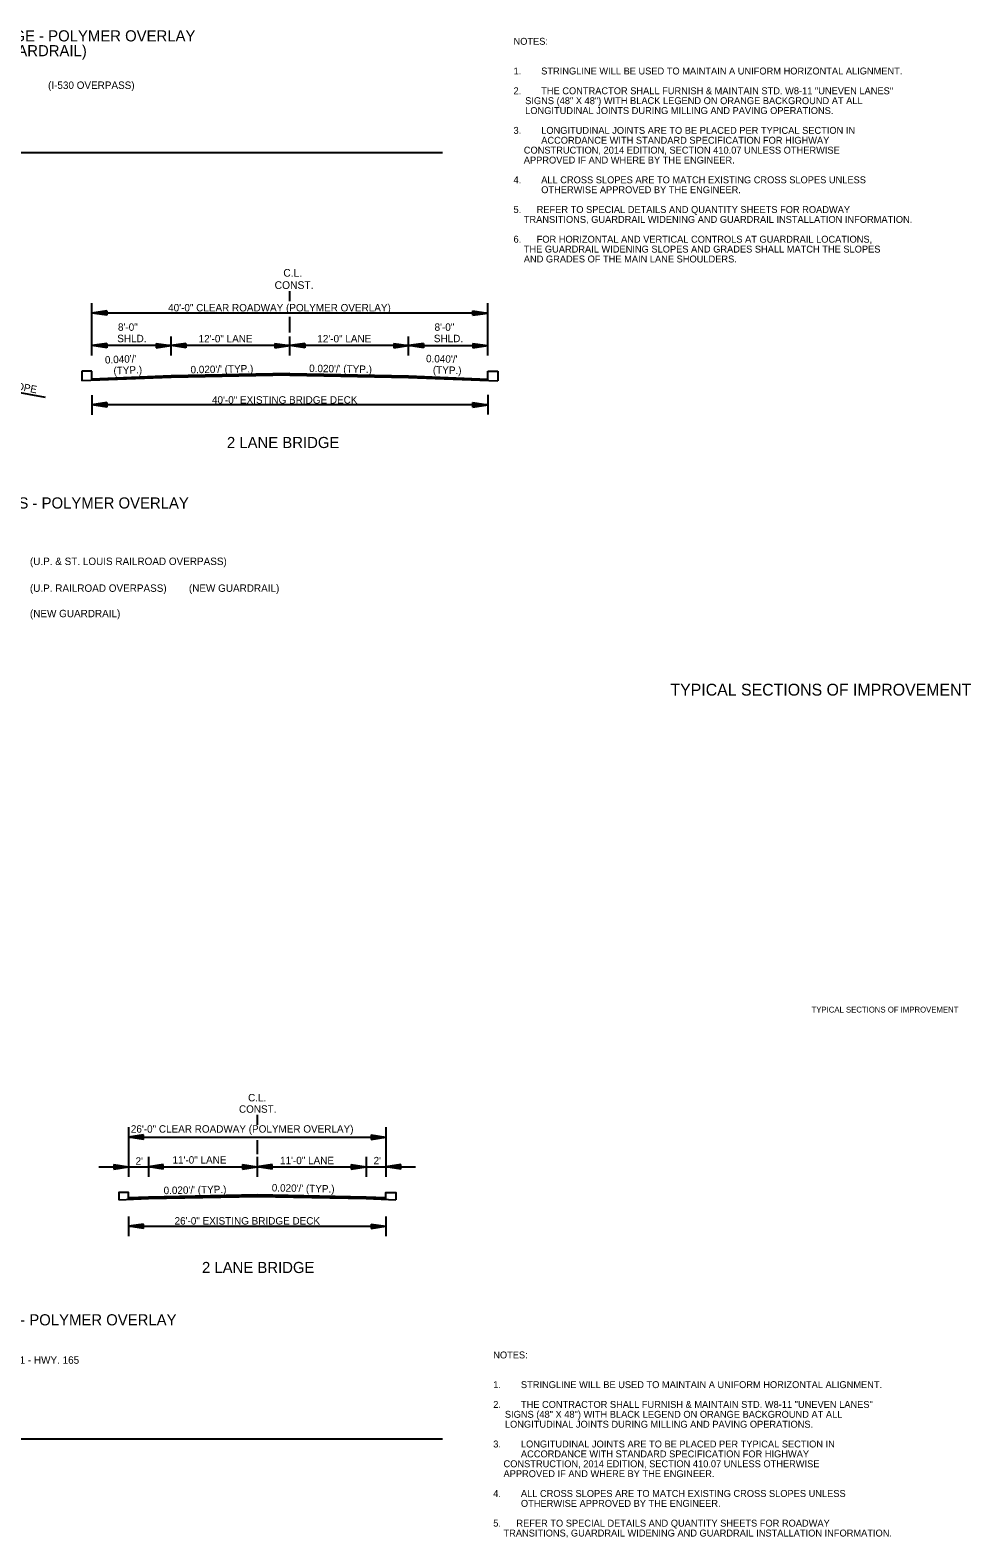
# Model space of a CAD drawing. Extents: x 545241 to 1930787, y -1971772 to 596640.
# Drawn here: x 547317 to 548268, y -1951823 to -1950299 of the extents above; entities that cross this region are included whole.
import ezdxf

# ---------------------------------------------------------------- set-up
doc = ezdxf.new("R2010")
doc.units = 0
for name, color, linetype in [('R_Border', 7, 'Continuous'), ('R_Border Notes', 7, 'Continuous'), ('R_Border Prem', 7, 'Continuous'), ('R_Draft', 7, 'Continuous')]:
    doc.layers.add(name, color=color, linetype=linetype)

# ---------------------------------------------------------------- blocks, each defined once
blk = doc.blocks.new('ARROW')
at = {"layer": 'R_Draft'}
for p, q in [((-2, 0.3), (0, 0)), ((-2, 0.3), (-2, -0.3)), ((-2, 0.25), (-0.334, 0)), ((-2, 0.199), (-0.678, 0)), ((-2, 0.149), (-1.011, 0)), ((-2, 0.097), (-1.35, 0)), ((-2, 0.047), (-1.684, 0)), ((-2, -0.3), (0, 0)), ((-2, -0.098), (-1.35, 0)), ((-2, -0.199), (-0.678, 0)), ((-2, -0.25), (-0.334, 0)), ((-2, -0.149), (-1.011, 0)), ((-2, -0.047), (-1.684, 0))]:
    blk.add_line(p, q, dxfattribs=at)

msp = doc.modelspace()

# ---------------------------------------------------------------- linework, layer by layer
at = {"layer": 'R_Border'}
for p, q in [((546887.2, -1950422.9), (547733.9, -1950422.9)), ((547369.3, -1950643.9), (547369.3, -1950653.7)), ((547379.5, -1950643.9), (547369.3, -1950643.9)), ((547379.5, -1950653.3), (547379.5, -1950643.9)), ((547779.5, -1950653.3), (547779.5, -1950643.9)), ((547779.5, -1950643.9), (547789.7, -1950643.9)), ((547789.7, -1950643.9), (547789.7, -1950653.7)), ((547546.6, -1951395.5), (547546.6, -1951405.5)), ((547416.6, -1951408), (547416.6, -1951458)), ((547676.6, -1951408), (547676.6, -1951458)), ((547416.6, -1951418), (547676.6, -1951418)), ((547546.6, -1951421), (547546.6, -1951435)), ((547436.6, -1951438), (547436.6, -1951458)), ((547546.6, -1951438), (547546.6, -1951458)), ((547656.6, -1951438), (547656.6, -1951458)), ((547386.6, -1951448), (547706.6, -1951448)), ((547416.6, -1951498), (547416.6, -1951518)), ((547676.6, -1951498), (547676.6, -1951518)), ((547416.6, -1951508), (547676.6, -1951508)), ((546887.2, -1951722.9), (547733.9, -1951722.9))]:
    msp.add_line(p, q, dxfattribs=at)
for points in [[(547416.6, -1951480.5), (547416.6, -1951474), (547406.6, -1951474), (547406.6, -1951481.2)], [(547406.6, -1951481.2), (547436.6, -1951480), (547546.6, -1951477.8), (547656.6, -1951480), (547686.6, -1951481.2)], [(547416.6, -1951479), (547436.6, -1951478.2), (547546.6, -1951476), (547656.6, -1951478.2), (547676.6, -1951479)], [(547416.6, -1951479.3), (547436.6, -1951478.5), (547546.6, -1951476.3), (547656.6, -1951478.5), (547676.6, -1951479.3)], [(547416.6, -1951479.6), (547436.6, -1951478.8), (547546.6, -1951476.6), (547656.6, -1951478.8), (547676.6, -1951479.6)], [(547416.6, -1951479.9), (547436.6, -1951479.1), (547546.6, -1951476.9), (547656.6, -1951479.1), (547676.6, -1951479.9)], [(547416.6, -1951480.2), (547436.6, -1951479.4), (547546.6, -1951477.2), (547656.6, -1951479.4), (547676.6, -1951480.2)], [(547416.6, -1951480.5), (547436.6, -1951479.7), (547546.6, -1951477.5), (547656.6, -1951479.7), (547676.6, -1951480.5)], [(547676.6, -1951480.5), (547676.6, -1951474), (547686.6, -1951474), (547686.6, -1951481.2)]]:
    msp.add_lwpolyline(points, dxfattribs=at)
at = {"layer": 'R_Draft'}
for p, q in [((547579.5, -1950572.9), (547579.5, -1950562.9)), ((547379.5, -1950627.9), (547379.5, -1950575.2)), ((547394.5, -1950582.8), (547379.5, -1950585.1)), ((547779.5, -1950585.1), (547379.5, -1950585.1)), ((547394.5, -1950587.3), (547379.5, -1950585.1)), ((547394.5, -1950583.2), (547382, -1950585.1)), ((547394.5, -1950586.9), (547382, -1950585.1)), ((547394.5, -1950583.6), (547384.6, -1950585.1)), ((547394.5, -1950586.6), (547384.6, -1950585.1)), ((547394.5, -1950584), (547387.1, -1950585.1)), ((547394.5, -1950586.2), (547387.1, -1950585.1)), ((547394.5, -1950584.3), (547389.6, -1950585.1)), ((547394.5, -1950585.8), (547389.6, -1950585.1)), ((547394.5, -1950584.7), (547392.1, -1950585.1)), ((547394.5, -1950585.4), (547392.1, -1950585.1)), ((547394.5, -1950582.8), (547394.5, -1950587.3)), ((547579.5, -1950604.6), (547579.5, -1950589)), ((547764.5, -1950582.8), (547779.5, -1950585.1)), ((547764.5, -1950587.3), (547764.5, -1950582.8)), ((547764.5, -1950583.2), (547777, -1950585.1)), ((547764.5, -1950583.6), (547774.4, -1950585.1)), ((547764.5, -1950584), (547771.9, -1950585.1)), ((547764.5, -1950584.3), (547769.4, -1950585.1)), ((547764.5, -1950584.7), (547766.9, -1950585.1)), ((547764.5, -1950587.3), (547779.5, -1950585.1)), ((547764.5, -1950585.8), (547769.4, -1950585.1)), ((547764.5, -1950586.6), (547774.4, -1950585.1)), ((547764.5, -1950586.9), (547777, -1950585.1)), ((547764.5, -1950586.2), (547771.9, -1950585.1)), ((547764.5, -1950585.4), (547766.9, -1950585.1)), ((547779.5, -1950627.9), (547779.5, -1950575.2)), ((547394.5, -1950615.7), (547379.5, -1950617.9)), ((547459.5, -1950617.9), (547379.5, -1950617.9)), ((547394.5, -1950620.2), (547379.5, -1950617.9)), ((547394.5, -1950616), (547382, -1950617.9)), ((547394.5, -1950619.8), (547382, -1950617.9)), ((547394.5, -1950616.4), (547384.6, -1950617.9)), ((547394.5, -1950619.4), (547384.6, -1950617.9)), ((547394.5, -1950616.8), (547387.1, -1950617.9)), ((547394.5, -1950619), (547387.1, -1950617.9)), ((547394.5, -1950617.2), (547389.6, -1950617.9)), ((547394.5, -1950618.6), (547389.6, -1950617.9)), ((547394.5, -1950617.6), (547392.1, -1950617.9)), ((547394.5, -1950618.3), (547392.1, -1950617.9)), ((547394.5, -1950615.7), (547394.5, -1950620.2)), ((547444.5, -1950615.7), (547459.5, -1950617.9)), ((547444.5, -1950615.7), (547444.5, -1950620.2)), ((547444.5, -1950616), (547457, -1950617.9)), ((547444.5, -1950616.4), (547454.4, -1950617.9)), ((547444.5, -1950616.8), (547451.9, -1950617.9)), ((547444.5, -1950617.2), (547449.4, -1950617.9)), ((547444.5, -1950617.6), (547446.9, -1950617.9)), ((547444.5, -1950620.2), (547459.5, -1950617.9)), ((547444.5, -1950618.6), (547449.4, -1950617.9)), ((547444.5, -1950619.4), (547454.4, -1950617.9)), ((547444.5, -1950619.8), (547457, -1950617.9)), ((547444.5, -1950619), (547451.9, -1950617.9)), ((547444.5, -1950618.3), (547446.9, -1950617.9)), ((547459.5, -1950627.9), (547459.5, -1950608.7)), ((547474.5, -1950615.7), (547459.5, -1950617.9)), ((547579.5, -1950617.9), (547459.5, -1950617.9)), ((547474.5, -1950620.2), (547459.5, -1950617.9)), ((547474.5, -1950616), (547462, -1950617.9)), ((547474.5, -1950619.8), (547462, -1950617.9)), ((547474.5, -1950616.4), (547464.6, -1950617.9)), ((547474.5, -1950619.4), (547464.6, -1950617.9)), ((547474.5, -1950616.8), (547467.1, -1950617.9)), ((547474.5, -1950619), (547467.1, -1950617.9)), ((547474.5, -1950617.2), (547469.6, -1950617.9)), ((547474.5, -1950618.6), (547469.6, -1950617.9)), ((547474.5, -1950617.6), (547472.1, -1950617.9)), ((547474.5, -1950618.3), (547472.1, -1950617.9)), ((547474.5, -1950615.7), (547474.5, -1950620.2)), ((547564.5, -1950615.7), (547579.5, -1950617.9)), ((547564.5, -1950615.7), (547564.5, -1950620.2)), ((547564.5, -1950616), (547577, -1950617.9)), ((547564.5, -1950616.4), (547574.4, -1950617.9)), ((547564.5, -1950616.8), (547571.9, -1950617.9)), ((547564.5, -1950617.2), (547569.4, -1950617.9)), ((547564.5, -1950617.6), (547566.9, -1950617.9)), ((547564.5, -1950620.2), (547579.5, -1950617.9)), ((547564.5, -1950618.6), (547569.4, -1950617.9)), ((547564.5, -1950619.4), (547574.4, -1950617.9)), ((547564.5, -1950619.8), (547577, -1950617.9)), ((547564.5, -1950619), (547571.9, -1950617.9)), ((547564.5, -1950618.3), (547566.9, -1950617.9)), ((547579.5, -1950627.9), (547579.5, -1950608.7)), ((547594.5, -1950615.7), (547579.5, -1950617.9)), ((547699.5, -1950617.9), (547579.5, -1950617.9)), ((547594.5, -1950620.2), (547579.5, -1950617.9)), ((547594.5, -1950616), (547582, -1950617.9)), ((547594.5, -1950619.8), (547582, -1950617.9)), ((547594.5, -1950616.4), (547584.6, -1950617.9)), ((547594.5, -1950619.4), (547584.6, -1950617.9)), ((547594.5, -1950616.8), (547587.1, -1950617.9)), ((547594.5, -1950619), (547587.1, -1950617.9)), ((547594.5, -1950617.2), (547589.6, -1950617.9)), ((547594.5, -1950618.6), (547589.6, -1950617.9)), ((547594.5, -1950617.6), (547592.1, -1950617.9)), ((547594.5, -1950618.3), (547592.1, -1950617.9)), ((547594.5, -1950615.7), (547594.5, -1950620.2)), ((547684.5, -1950615.7), (547699.5, -1950617.9)), ((547684.5, -1950615.7), (547684.5, -1950620.2)), ((547684.5, -1950616), (547697, -1950617.9)), ((547684.5, -1950616.4), (547694.4, -1950617.9)), ((547684.5, -1950616.8), (547691.9, -1950617.9)), ((547684.5, -1950617.2), (547689.4, -1950617.9)), ((547684.5, -1950617.6), (547686.9, -1950617.9)), ((547684.5, -1950620.2), (547699.5, -1950617.9)), ((547684.5, -1950618.6), (547689.4, -1950617.9)), ((547684.5, -1950619.4), (547694.4, -1950617.9)), ((547684.5, -1950619.8), (547697, -1950617.9)), ((547684.5, -1950619), (547691.9, -1950617.9)), ((547684.5, -1950618.3), (547686.9, -1950617.9)), ((547699.5, -1950627.9), (547699.5, -1950608.7)), ((547714.5, -1950615.7), (547699.5, -1950617.9)), ((547699.5, -1950617.9), (547779.5, -1950617.9)), ((547714.5, -1950620.2), (547699.5, -1950617.9)), ((547714.5, -1950616), (547702, -1950617.9)), ((547714.5, -1950619.8), (547702, -1950617.9)), ((547714.5, -1950616.4), (547704.6, -1950617.9)), ((547714.5, -1950619.4), (547704.6, -1950617.9)), ((547714.5, -1950616.8), (547707.1, -1950617.9)), ((547714.5, -1950619), (547707.1, -1950617.9)), ((547714.5, -1950617.2), (547709.6, -1950617.9)), ((547714.5, -1950618.6), (547709.6, -1950617.9)), ((547714.5, -1950617.6), (547712.1, -1950617.9)), ((547714.5, -1950618.3), (547712.1, -1950617.9)), ((547714.5, -1950615.7), (547714.5, -1950620.2)), ((547764.5, -1950615.7), (547779.5, -1950617.9)), ((547764.5, -1950615.7), (547764.5, -1950620.2)), ((547764.5, -1950616), (547777, -1950617.9)), ((547764.5, -1950616.4), (547774.4, -1950617.9)), ((547764.5, -1950616.8), (547771.9, -1950617.9)), ((547764.5, -1950617.2), (547769.4, -1950617.9)), ((547764.5, -1950617.6), (547766.9, -1950617.9)), ((547764.5, -1950620.2), (547779.5, -1950617.9)), ((547764.5, -1950618.6), (547769.4, -1950617.9)), ((547764.5, -1950619.4), (547774.4, -1950617.9)), ((547764.5, -1950619.8), (547777, -1950617.9)), ((547764.5, -1950619), (547771.9, -1950617.9)), ((547764.5, -1950618.3), (547766.9, -1950617.9)), ((547459.5, -1950650.1), (547369.3, -1950653.7)), ((547459.5, -1950648.6), (547379.5, -1950651.8)), ((547459.5, -1950648.9), (547379.5, -1950652.1)), ((547459.5, -1950649.2), (547379.5, -1950652.4)), ((547459.5, -1950649.5), (547379.5, -1950652.7)), ((547459.5, -1950649.8), (547379.5, -1950653)), ((547579.5, -1950646.2), (547459.5, -1950648.6)), ((547579.5, -1950646.5), (547459.5, -1950648.9)), ((547579.5, -1950646.8), (547459.5, -1950649.2)), ((547579.5, -1950647.1), (547459.5, -1950649.5)), ((547579.5, -1950647.4), (547459.5, -1950649.8)), ((547579.5, -1950647.7), (547459.5, -1950650.1)), ((547579.5, -1950647.9), (547459.5, -1950650.3)), ((547579.5, -1950646.2), (547699.5, -1950648.6)), ((547579.5, -1950646.5), (547699.5, -1950648.9)), ((547579.5, -1950646.8), (547699.5, -1950649.2)), ((547579.5, -1950647.1), (547699.5, -1950649.5)), ((547579.5, -1950647.4), (547699.5, -1950649.8)), ((547579.5, -1950647.7), (547699.5, -1950650.1)), ((547579.5, -1950647.9), (547699.5, -1950650.3)), ((547699.5, -1950648.6), (547779.5, -1950651.8)), ((547699.5, -1950648.9), (547779.5, -1950652.1)), ((547699.5, -1950649.2), (547779.5, -1950652.4)), ((547699.5, -1950649.5), (547779.5, -1950652.7)), ((547699.5, -1950649.8), (547779.5, -1950653)), ((547699.5, -1950650.1), (547789.7, -1950653.7)), ((547232.1, -1950651.8), (547332.1, -1950670.2)), ((547379.5, -1950667.9), (547379.5, -1950687.9)), ((547394.5, -1950675.6), (547379.5, -1950677.9)), ((547394.5, -1950680.1), (547379.5, -1950677.9)), ((547779.5, -1950677.9), (547379.5, -1950677.9)), ((547394.5, -1950676), (547382, -1950677.9)), ((547394.5, -1950679.8), (547382, -1950677.9)), ((547394.5, -1950676.4), (547384.6, -1950677.9)), ((547394.5, -1950679.4), (547384.6, -1950677.9)), ((547394.5, -1950676.8), (547387.1, -1950677.9)), ((547394.5, -1950679), (547387.1, -1950677.9)), ((547394.5, -1950677.1), (547389.6, -1950677.9)), ((547394.5, -1950678.6), (547389.6, -1950677.9)), ((547394.5, -1950677.5), (547392.1, -1950677.9)), ((547394.5, -1950678.2), (547392.1, -1950677.9)), ((547394.5, -1950675.6), (547394.5, -1950680.1)), ((547764.5, -1950675.6), (547779.5, -1950677.9)), ((547764.5, -1950680.1), (547764.5, -1950675.6)), ((547764.5, -1950676), (547777, -1950677.9)), ((547764.5, -1950676.4), (547774.4, -1950677.9)), ((547764.5, -1950676.8), (547771.9, -1950677.9)), ((547764.5, -1950677.1), (547769.4, -1950677.9)), ((547764.5, -1950677.5), (547766.9, -1950677.9)), ((547764.5, -1950680.1), (547779.5, -1950677.9)), ((547764.5, -1950678.6), (547769.4, -1950677.9)), ((547764.5, -1950679.4), (547774.4, -1950677.9)), ((547764.5, -1950679.8), (547777, -1950677.9)), ((547764.5, -1950679), (547771.9, -1950677.9)), ((547764.5, -1950678.2), (547766.9, -1950677.9)), ((547779.5, -1950667.6), (547779.5, -1950687.6))]:
    msp.add_line(p, q, dxfattribs=at)

# ---------------------------------------------------------------- block references
at = {"layer": 'R_Border', "xscale": 7.5, "yscale": 7.5, "rotation": 180}
for p in [(547416.6, -1951418), (547436.6, -1951448), (547546.6, -1951448), (547676.6, -1951448), (547416.6, -1951508)]:
    msp.add_blockref('ARROW', p, dxfattribs=at)
at = {"layer": 'R_Border', "xscale": 7.5, "yscale": 7.5}
for p in [(547676.6, -1951418), (547416.6, -1951448), (547546.6, -1951448), (547656.6, -1951448), (547676.6, -1951508)]:
    msp.add_blockref('ARROW', p, dxfattribs=at)

# ---------------------------------------------------------------- texts
at = {"layer": 'R_Border'}
for s, height, p in [('25 FT. CLEAR ROADWAY BRIDGE - POLYMER OVERLAY', 11.25, (547080.3, -1950310.5)), ('(NEW GUARDRAIL)', 11.25, (547237.2, -1950325.5)), ('C.L.', 7.5, (547537.3, -1951381.8)), ('CONST.', 7.5, (547528.1, -1951393.3)), ('26\'-0" CLEAR ROADWAY (POLYMER OVERLAY)', 7.5, (547418.8, -1951413.4)), ("2'", 7.5, (547423.6, -1951445.8)), ('11\'-0" LANE', 7.5, (547460.9, -1951444.7)), ('11\'-0" LANE', 7.5, (547569.6, -1951445.3)), ("2'", 7.5, (547664.1, -1951445.4)), ('26\'-0" EXISTING BRIDGE DECK', 7.5, (547463, -1951506.3)), ('2 LANE BRIDGE', 11.25, (547490.7, -1951555.3)), ('26 FT. CLEAR ROADWAY BRIDGE - POLYMER OVERLAY', 11.25, (547061.2, -1951608.2)), ('- BR NO. 02891 - HWY. 165', 7.5, (547240.6, -1951647))]:
    msp.add_text(s, height=height, dxfattribs=at).set_placement(p)
for s, height, rotation, p in [('TYPICAL SECTIONS OF IMPROVEMENT', 12, 360, (547964.2, -1950971.7)), ("0.020'/' (TYP.)", 7.5, 1.1458, (547452, -1951475.6)), ("0.020'/' (TYP.)", 7.5, 358.8542, (547561.2, -1951472.8))]:
    msp.add_text(s, height=height, rotation=rotation, dxfattribs=at).set_placement(p)
at = {"layer": 'R_Border Notes'}
for s, p in [('NOTES: ', (547805.6, -1950313.9)), ('1.', (547805.6, -1950343.9)), ('STRINGLINE WILL BE USED TO MAINTAIN A UNIFORM HORIZONTAL ALIGNMENT.', (547833.6, -1950343.9)), ('2.', (547805.6, -1950363.9)), ('THE CONTRACTOR SHALL FURNISH & MAINTAIN STD. W8-11 "UNEVEN LANES" ', (547833.6, -1950363.9)), ('    SIGNS (48" X 48") WITH BLACK LEGEND ON ORANGE BACKGROUND AT ALL ', (547807, -1950373.9)), ('    LONGITUDINAL JOINTS DURING MILLING AND PAVING OPERATIONS.', (547807, -1950383.9)), ('3.', (547805.6, -1950403.9)), ('LONGITUDINAL JOINTS ARE TO BE PLACED PER TYPICAL SECTION IN ', (547833.6, -1950403.9)), ('    CONSTRUCTION, 2014 EDITION, SECTION 410.07 UNLESS OTHERWISE', (547805.6, -1950423.9)), ('ACCORDANCE WITH STANDARD SPECIFICATION FOR HIGHWAY', (547833.6, -1950413.9)), ('    APPROVED IF AND WHERE BY THE ENGINEER.', (547805.6, -1950433.9)), ('4.', (547805.6, -1950453.9)), ('ALL CROSS SLOPES ARE TO MATCH EXISTING CROSS SLOPES UNLESS ', (547833.6, -1950453.9)), ('OTHERWISE APPROVED BY THE ENGINEER.', (547833.6, -1950463.9)), ('5.      REFER TO SPECIAL DETAILS AND QUANTITY SHEETS FOR ROADWAY', (547805.6, -1950483.9)), ('    TRANSITIONS, GUARDRAIL WIDENING AND GUARDRAIL INSTALLATION INFORMATION.', (547805.6, -1950493.9)), ('6.      FOR HORIZONTAL AND VERTICAL CONTROLS AT GUARDRAIL LOCATIONS,', (547805.6, -1950513.9)), ('    AND GRADES OF THE MAIN LANE SHOULDERS.  ', (547805.6, -1950533.9)), ('    THE GUARDRAIL WIDENING SLOPES AND GRADES SHALL MATCH THE SLOPES', (547805.6, -1950523.9)), ('NOTES: ', (547785.1, -1951641.6)), ('1.', (547785.1, -1951671.6)), ('STRINGLINE WILL BE USED TO MAINTAIN A UNIFORM HORIZONTAL ALIGNMENT.', (547813.1, -1951671.6)), ('2.', (547785.1, -1951691.6)), ('THE CONTRACTOR SHALL FURNISH & MAINTAIN STD. W8-11 "UNEVEN LANES" ', (547813.1, -1951691.6)), ('    SIGNS (48" X 48") WITH BLACK LEGEND ON ORANGE BACKGROUND AT ALL ', (547786.5, -1951701.6)), ('    LONGITUDINAL JOINTS DURING MILLING AND PAVING OPERATIONS.', (547786.5, -1951711.6)), ('3.', (547785.1, -1951731.6)), ('LONGITUDINAL JOINTS ARE TO BE PLACED PER TYPICAL SECTION IN ', (547813.1, -1951731.6)), ('    CONSTRUCTION, 2014 EDITION, SECTION 410.07 UNLESS OTHERWISE', (547785.1, -1951751.6)), ('ACCORDANCE WITH STANDARD SPECIFICATION FOR HIGHWAY', (547813.1, -1951741.6)), ('    APPROVED IF AND WHERE BY THE ENGINEER.', (547785.1, -1951761.6)), ('4.', (547785.1, -1951781.6)), ('ALL CROSS SLOPES ARE TO MATCH EXISTING CROSS SLOPES UNLESS ', (547813.1, -1951781.6)), ('OTHERWISE APPROVED BY THE ENGINEER.', (547813.1, -1951791.6)), ('5.      REFER TO SPECIAL DETAILS AND QUANTITY SHEETS FOR ROADWAY', (547785.1, -1951811.6)), ('    TRANSITIONS, GUARDRAIL WIDENING AND GUARDRAIL INSTALLATION INFORMATION.', (547785.1, -1951821.6))]:
    msp.add_text(s, height=7, dxfattribs=at).set_placement(p)
at = {"layer": 'R_Border Prem'}
msp.add_text('TYPICAL SECTIONS OF IMPROVEMENT', height=5.862, rotation=360, dxfattribs=at).set_placement((548106.8, -1951292))
at = {"layer": 'R_Draft'}
for s, height, p in [('(I-530 OVERPASS)', 7.5, (547335.1, -1950358.5)), ('C.L.', 7.8, (547572.9, -1950548.3)), ('CONST.', 7.8, (547564.1, -1950560.7)), ('40\'-0" CLEAR ROADWAY (POLYMER OVERLAY)', 7.5, (547456.5, -1950583.4)), ('8\'-0"', 7.5, (547405.8, -1950603)), ('8\'-0"', 7.5, (547725.8, -1950603)), ('SHLD.', 7.5, (547405.1, -1950614.5)), ('12\'-0" LANE', 7.5, (547487.3, -1950614.7)), ('12\'-0" LANE', 7.5, (547607.3, -1950614.7)), ('SHLD.', 7.5, (547725.1, -1950614.5)), ('40\'-0" EXISTING BRIDGE DECK', 7.5, (547500.8, -1950676.6)), ('2 LANE BRIDGE', 11.25, (547515.9, -1950721.5)), ('40 FT. CLEAR ROADWAY BRIDGES - POLYMER OVERLAY', 11.25, (547063.6, -1950782.6)), ('(U.P. & ST. LOUIS RAILROAD OVERPASS)', 7.5, (547316.8, -1950839.7)), ('(U.P. RAILROAD OVERPASS)', 7.5, (547316.8, -1950866.8)), ('(NEW GUARDRAIL)', 7.5, (547477.5, -1950866.8)), ('(NEW GUARDRAIL)', 7.5, (547316.8, -1950892.5))]:
    msp.add_text(s, height=height, dxfattribs=at).set_placement(p)
for s, rotation, p in [("  0.040'/'", 2.448, (547387.2, -1950636.4)), ("0.040'/'", 358.6816, (547717.1, -1950634.7)), ('EXIST. SLOPE', 349.1171, (547256.4, -1950653.4)), (' (TYP.)', 2.448, (547398.6, -1950647.2)), ("0.020'/' (TYP.)", 0.9719, (547479.2, -1950646)), ("0.020'/' (TYP.)", 359.0281, (547599, -1950644.6)), ('(TYP.)', 358.6816, (547724, -1950646.1))]:
    msp.add_text(s, height=7.5, rotation=rotation, dxfattribs=at).set_placement(p)

doc.saveas('drawing.dxf')
